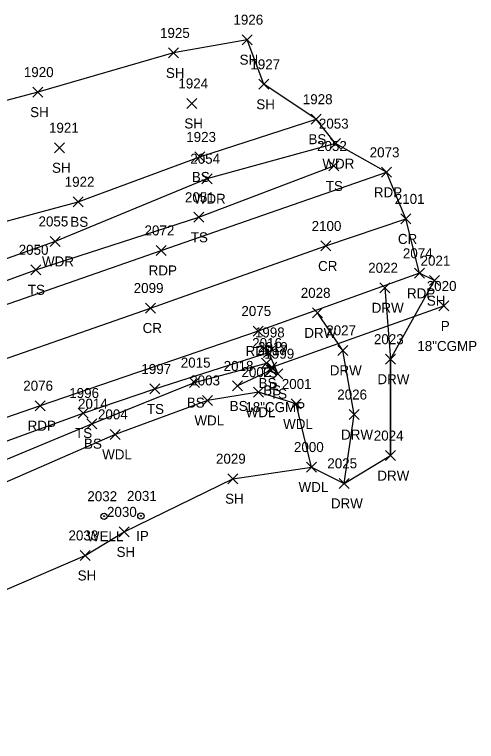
# Model space of a CAD drawing. Extents: x 1526508 to 1531550, y 369926 to 373082.
# Drawn here: x 1531457.6 to 1531549.9, y 370192.4 to 370337.7 of the extents above; entities that cross this region are included whole.
import ezdxf

# ---------------------------------------------------------------- set-up
doc = ezdxf.new("R2010")
doc.units = 0
for name, color, linetype in [('D_A', 7, 'Continuous'), ('D_C', 7, 'Continuous'), ('D_I', 7, 'Continuous'), ('D_TIC', 7, 'Continuous'), ('DCP', 7, 'Continuous'), ('L_A', 7, 'Continuous'), ('L_I', 7, 'Continuous'), ('L_TIC', 7, 'Continuous'), ('LAWA', 7, 'Continuous'), ('LELB', 7, 'Continuous'), ('LSOGP', 7, 'Continuous'), ('M_A', 7, 'Continuous'), ('M_I', 7, 'Continuous'), ('MPIR', 7, 'Continuous'), ('P_A', 7, 'Continuous'), ('P_I', 7, 'Continuous'), ('P_TIC', 7, 'Continuous'), ('PET', 7, 'Continuous'), ('PRC', 7, 'Continuous'), ('R_A', 7, 'Continuous'), ('R_I', 7, 'Continuous'), ('R_TIC', 7, 'Continuous'), ('RDW', 7, 'Continuous'), ('U_A', 7, 'Continuous'), ('U_I', 7, 'Continuous'), ('UWW', 7, 'Continuous')]:
    doc.layers.add(name, color=color, linetype=linetype)

msp = doc.modelspace()

# ---------------------------------------------------------------- linework, layer by layer
at = {"layer": 'D_TIC'}
for points in [[(1531542.39, 370278.49), (1531544.39, 370280.49)], [(1531544.39, 370278.49), (1531542.39, 370280.49)], [(1531508.03, 370266.27), (1531510.03, 370268.27)], [(1531510.03, 370266.27), (1531508.03, 370268.27)]]:
    msp.add_lwpolyline(points, dxfattribs=at)
at = {"layer": 'DCP'}
msp.add_lwpolyline([(1531509.03, 370267.27), (1531543.39, 370279.49)], dxfattribs=at)
at = {"layer": 'L_TIC'}
for points in [[(1531503.1, 370331.72), (1531505.1, 370333.72)], [(1531505.1, 370331.72), (1531503.1, 370333.72)], [(1531488.37, 370329.07), (1531490.37, 370331.07)], [(1531490.37, 370329.07), (1531488.37, 370331.07)], [(1531506.43, 370322.8), (1531508.43, 370324.8)], [(1531508.43, 370322.8), (1531506.43, 370324.8)], [(1531461.26, 370321.24), (1531463.26, 370323.24)], [(1531463.26, 370321.24), (1531461.26, 370323.24)], [(1531492.05, 370318.97), (1531494.05, 370320.97)], [(1531494.05, 370318.97), (1531492.05, 370320.97)], [(1531516.9, 370315.82), (1531518.9, 370317.82)], [(1531518.9, 370315.82), (1531516.9, 370317.82)], [(1531520.76, 370310.94), (1531522.76, 370312.94)], [(1531522.76, 370310.94), (1531520.76, 370312.94)], [(1531465.62, 370310.11), (1531467.62, 370312.11)], [(1531467.62, 370310.11), (1531465.62, 370312.11)], [(1531493.61, 370308.28), (1531495.61, 370310.28)], [(1531495.61, 370308.28), (1531493.61, 370310.28)], [(1531520.4, 370306.47), (1531522.4, 370308.47)], [(1531522.4, 370306.47), (1531520.4, 370308.47)], [(1531495.07, 370303.92), (1531497.07, 370305.92)], [(1531497.07, 370303.92), (1531495.07, 370305.92)], [(1531469.33, 370299.31), (1531471.33, 370301.31)], [(1531471.33, 370299.31), (1531469.33, 370301.31)], [(1531493.43, 370296.22), (1531495.43, 370298.22)], [(1531495.43, 370296.22), (1531493.43, 370298.22)], [(1531464.75, 370291.39), (1531466.75, 370293.39)], [(1531466.75, 370291.39), (1531464.75, 370293.39)], [(1531460.87, 370285.72), (1531462.87, 370287.72)], [(1531462.87, 370285.72), (1531460.87, 370287.72)], [(1531540.51, 370283.55), (1531542.51, 370285.55)], [(1531542.51, 370283.55), (1531540.51, 370285.55)], [(1531507.33, 370269.2), (1531509.33, 370271.2)], [(1531509.33, 370269.2), (1531507.33, 370271.2)], [(1531506.93, 370267.08), (1531508.93, 370269.08)], [(1531508.93, 370267.08), (1531506.93, 370269.08)], [(1531507.86, 370265.64), (1531509.86, 370267.64)], [(1531509.86, 370265.64), (1531507.86, 370267.64)], [(1531509.24, 370264.95), (1531511.24, 370266.95)], [(1531511.24, 370264.95), (1531509.24, 370266.95)], [(1531492.6, 370263.17), (1531494.6, 370265.17)], [(1531494.6, 370263.17), (1531492.6, 370265.17)], [(1531484.65, 370261.9), (1531486.65, 370263.9)], [(1531486.65, 370261.9), (1531484.65, 370263.9)], [(1531501.17, 370262.5), (1531503.17, 370264.5)], [(1531503.17, 370262.5), (1531501.17, 370264.5)], [(1531505.38, 370261.26), (1531507.38, 370263.26)], [(1531507.38, 370261.26), (1531505.38, 370263.26)], [(1531495.14, 370259.61), (1531497.14, 370261.61)], [(1531497.14, 370259.61), (1531495.14, 370261.61)], [(1531512.86, 370258.9), (1531514.86, 370260.9)], [(1531514.86, 370258.9), (1531512.86, 370260.9)], [(1531470.3, 370257.09), (1531472.3, 370259.09)], [(1531472.3, 370257.09), (1531470.3, 370259.09)], [(1531472.07, 370254.96), (1531474.07, 370256.96)], [(1531474.07, 370254.96), (1531472.07, 370256.96)], [(1531476.71, 370252.82), (1531478.71, 370254.82)], [(1531478.71, 370252.82), (1531476.71, 370254.82)], [(1531515.95, 370246.29), (1531517.95, 370248.29)], [(1531517.95, 370246.29), (1531515.95, 370248.29)], [(1531500.2, 370243.96), (1531502.2, 370245.96)], [(1531502.2, 370243.96), (1531500.2, 370245.96)], [(1531478.51, 370233.33), (1531480.51, 370235.33)], [(1531480.51, 370233.33), (1531478.51, 370235.33)], [(1531470.74, 370228.62), (1531472.74, 370230.62)], [(1531472.74, 370228.62), (1531470.74, 370230.62)]]:
    msp.add_lwpolyline(points, dxfattribs=at)
at = {"layer": 'LAWA'}
for points in [[(1531521.76, 370311.94), (1531496.07, 370304.92), (1531465.75, 370292.39), (1531436.88, 370282.15), (1531407.49, 370272.6), (1531388.76, 370267.94), (1531371.46, 370261.74), (1531353.51, 370253.07)], [(1531516.95, 370247.29), (1531513.86, 370259.9), (1531506.38, 370262.26), (1531496.14, 370260.61), (1531477.71, 370253.82), (1531453.39, 370243.21), (1531431.41, 370234.22), (1531411.87, 370226.08), (1531392.93, 370218.41), (1531374.28, 370205.66)]]:
    msp.add_lwpolyline(points, dxfattribs=at)
at = {"layer": 'LELB'}
for points in [[(1531144.65, 370206.06), (1531164.57, 370210.72), (1531180.3, 370218.31), (1531196.61, 370223.05), (1531216.18, 370227.2), (1531246.26, 370234.32), (1531259.5, 370237.9), (1531291.92, 370247.44), (1531321.67, 370253.97), (1531341.88, 370260.29), (1531377.42, 370272.37), (1531403.24, 370281.83), (1531425.1, 370287.02), (1531443.59, 370293.1), (1531470.33, 370300.31), (1531494.61, 370309.28), (1531517.9, 370316.82)], [(1531363.93, 370252.47), (1531390.95, 370261.46), (1531419.32, 370270.89), (1531442.26, 370279.58), (1531461.87, 370286.72), (1531494.43, 370297.22), (1531521.4, 370307.47)], [(1531373.54, 370214.88), (1531392.5, 370225.12), (1531411.75, 370234.05), (1531446.79, 370249.15), (1531471.3, 370258.09), (1531485.65, 370262.9), (1531508.33, 370270.2), (1531510.24, 370265.95)], [(1531371.86, 370211.77), (1531393.12, 370222.78), (1531419.45, 370234.98), (1531448.33, 370245.69), (1531473.07, 370255.96), (1531493.6, 370264.17), (1531507.93, 370268.08), (1531508.86, 370266.64), (1531502.17, 370263.5)]]:
    msp.add_lwpolyline(points, dxfattribs=at)
at = {"layer": 'LSOGP'}
msp.add_lwpolyline([(1531434.17, 370213.44), (1531471.74, 370229.62), (1531479.51, 370234.33), (1531501.2, 370244.96), (1531516.95, 370247.29), (1531523.45, 370244.03), (1531532.73, 370249.58), (1531532.74, 370259.21), (1531532.75, 370268.85), (1531541.51, 370284.55), (1531538.54, 370286.02), (1531535.78, 370296.89), (1531531.91, 370306.21), (1531521.76, 370311.94), (1531517.9, 370316.82), (1531507.43, 370323.8), (1531504.1, 370332.72), (1531489.37, 370330.07), (1531462.26, 370322.24), (1531445.4, 370317.76)], dxfattribs=at)
at = {"layer": 'MPIR'}
for radius in [0.625, 0.0833]:
    msp.add_circle((1531482.86, 370237.52), radius, dxfattribs=at)
at = {"layer": 'P_TIC'}
for points in [[(1531530.91, 370305.21), (1531532.91, 370307.21)], [(1531532.91, 370305.21), (1531530.91, 370307.21)], [(1531534.78, 370295.89), (1531536.78, 370297.89)], [(1531536.78, 370295.89), (1531534.78, 370297.89)], [(1531485.93, 370289.59), (1531487.93, 370291.59)], [(1531487.93, 370289.59), (1531485.93, 370291.59)], [(1531518.83, 370290.48), (1531520.83, 370292.48)], [(1531520.83, 370290.48), (1531518.83, 370292.48)], [(1531537.54, 370285.02), (1531539.54, 370287.02)], [(1531539.54, 370285.02), (1531537.54, 370287.02)], [(1531483.78, 370278.08), (1531485.78, 370280.08)], [(1531485.78, 370278.08), (1531483.78, 370280.08)], [(1531505.28, 370273.48), (1531507.28, 370275.48)], [(1531507.28, 370273.48), (1531505.28, 370275.48)], [(1531461.76, 370258.55), (1531463.76, 370260.55)], [(1531463.76, 370258.55), (1531461.76, 370260.55)]]:
    msp.add_lwpolyline(points, dxfattribs=at)
at = {"layer": 'PET'}
for points in [[(1531036.19, 370150.91), (1531061.97, 370155.43), (1531104.8, 370164.58), (1531143.1, 370174.02), (1531180.11, 370184.91), (1531218.48, 370196.81), (1531260.06, 370210.9), (1531302.03, 370225.36), (1531352.57, 370243.2), (1531401.62, 370260.1), (1531448.12, 370277.05), (1531486.93, 370290.59), (1531531.91, 370306.21)], [(1531538.54, 370286.02), (1531506.28, 370274.48), (1531462.76, 370259.55), (1531429.61, 370248.08), (1531393.11, 370234.63), (1531350.62, 370219.92), (1531310.67, 370205.95), (1531271.31, 370192.3), (1531228.45, 370178.01), (1531188.4, 370165.28), (1531155.96, 370155.78), (1531116.2, 370145.37), (1531081.97, 370137.61), (1531057.06, 370132.93), (1531039.15, 370130.45)]]:
    msp.add_lwpolyline(points, dxfattribs=at)
at = {"layer": 'PRC'}
msp.add_lwpolyline([(1531037.76, 370140.53), (1531081.39, 370148.17), (1531130.61, 370160.04), (1531176.3, 370172.81), (1531216.72, 370185.49), (1531265.37, 370201.61), (1531315.14, 370219.14), (1531364.47, 370236.54), (1531403.01, 370250.24), (1531441.26, 370263.86), (1531484.78, 370279.08), (1531519.83, 370291.48), (1531535.78, 370296.89)], dxfattribs=at)
at = {"layer": 'R_TIC'}
for points in [[(1531530.61, 370282.12), (1531532.61, 370284.12)], [(1531532.61, 370282.12), (1531530.61, 370284.12)], [(1531517.14, 370277.11), (1531519.14, 370279.11)], [(1531519.14, 370277.11), (1531517.14, 370279.11)], [(1531522.23, 370269.62), (1531524.23, 370271.62)], [(1531524.23, 370269.62), (1531522.23, 370271.62)], [(1531531.75, 370267.85), (1531533.75, 370269.85)], [(1531533.75, 370267.85), (1531531.75, 370269.85)], [(1531524.48, 370256.78), (1531526.48, 370258.78)], [(1531526.48, 370256.78), (1531524.48, 370258.78)], [(1531531.73, 370248.58), (1531533.73, 370250.58)], [(1531533.73, 370248.58), (1531531.73, 370250.58)], [(1531522.45, 370243.03), (1531524.45, 370245.03)], [(1531524.45, 370243.03), (1531522.45, 370245.03)]]:
    msp.add_lwpolyline(points, dxfattribs=at)
at = {"layer": 'RDW'}
for points in [[(1531531.61, 370283.12), (1531532.75, 370268.85), (1531532.73, 370249.58)], [(1531523.45, 370244.03), (1531525.48, 370257.78), (1531523.23, 370270.62), (1531518.14, 370278.11)]]:
    msp.add_lwpolyline(points, dxfattribs=at)
at = {"layer": 'UWW'}
for radius in [0.625, 0.0833]:
    msp.add_circle((1531475.51, 370237.46), radius, dxfattribs=at)

# ---------------------------------------------------------------- texts
at = {"layer": 'D_A'}
for p in [(1531542.77, 370274.49), (1531508.41, 370262.27)]:
    msp.add_text('P', height=2, dxfattribs=at).set_placement(p)
at = {"layer": 'D_C'}
for p in [(1531538.09, 370270.49), (1531503.73, 370258.27)]:
    msp.add_text('18"CGMP', height=2, dxfattribs=at).set_placement(p)
at = {"layer": 'D_I'}
for s, p in [('2020', (1531539.97, 370282.49)), ('2019', (1531506.25, 370270.27))]:
    msp.add_text(s, height=2, dxfattribs=at).set_placement(p)
at = {"layer": 'L_A'}
for s, p in [('SH', (1531502.58, 370327.72)), ('SH', (1531487.86, 370325.07)), ('SH', (1531505.92, 370318.8)), ('SH', (1531460.74, 370317.24)), ('SH', (1531491.54, 370314.97)), ('BS', (1531516.34, 370311.82)), ('WDR', (1531519.12, 370306.94)), ('SH', (1531465.11, 370306.11)), ('BS', (1531493.05, 370304.28)), ('TS', (1531519.81, 370302.47)), ('WDR', (1531493.43, 370299.92)), ('BS', (1531468.77, 370295.31)), ('TS', (1531492.84, 370292.22)), ('WDR', (1531463.11, 370287.39)), ('TS', (1531460.28, 370281.72)), ('SH', (1531539.99, 370279.55)), ('TS', (1531506.74, 370265.2)), ('BS', (1531506.37, 370263.08)), ('BS', (1531507.3, 370261.64)), ('TS', (1531508.65, 370260.95)), ('BS', (1531492.04, 370259.17)), ('TS', (1531484.06, 370257.9)), ('BS', (1531500.61, 370258.5)), ('WDL', (1531503.79, 370257.26)), ('WDL', (1531493.56, 370255.61)), ('WDL', (1531511.28, 370254.9)), ('TS', (1531469.71, 370253.09)), ('BS', (1531471.51, 370250.96)), ('WDL', (1531475.13, 370248.82)), ('WDL', (1531514.36, 370242.29)), ('SH', (1531499.69, 370239.96)), ('SH', (1531478, 370229.33)), ('SH', (1531470.23, 370224.62))]:
    msp.add_text(s, height=2, dxfattribs=at).set_placement(p)
at = {"layer": 'L_I'}
for s, p in [('1926', (1531501.35, 370335.72)), ('1925', (1531486.68, 370333.07)), ('1927', (1531504.73, 370326.8)), ('1920', (1531459.48, 370325.24)), ('1924', (1531490.35, 370322.97)), ('1928', (1531515.21, 370319.82)), ('1921', (1531464.5, 370314.11)), ('2053', (1531518.42, 370314.94)), ('1923', (1531491.92, 370312.28)), ('2052', (1531518.06, 370310.47)), ('2054', (1531492.73, 370307.92)), ('1922', (1531467.64, 370303.31)), ('2051', (1531491.66, 370300.22)), ('2055', (1531462.41, 370295.39)), ('2050', (1531458.45, 370289.72)), ('2021', (1531538.73, 370287.55)), ('1998', (1531505.64, 370273.2)), ('2016', (1531505.1, 370271.08)), ('2017', (1531506.09, 370269.64)), ('1999', (1531507.54, 370268.95)), ('1997', (1531482.96, 370265.9)), ('2015', (1531490.83, 370267.17)), ('2018', (1531499.4, 370266.5)), ('2002', (1531502.96, 370265.26)), ('2003', (1531492.72, 370263.61)), ('2001', (1531511.01, 370262.9)), ('1996', (1531468.55, 370261.09)), ('2014', (1531470.3, 370258.96)), ('2004', (1531474.29, 370256.82)), ('2000', (1531513.44, 370250.29)), ('2029', (1531497.86, 370247.96)), ('2030', (1531476.09, 370237.33)), ('2033', (1531468.4, 370232.62))]:
    msp.add_text(s, height=2, dxfattribs=at).set_placement(p)
at = {"layer": 'M_A'}
msp.add_text('IP', height=2, dxfattribs=at).set_placement((1531481.91, 370232.52))
at = {"layer": 'M_I'}
msp.add_text('2031', height=2, dxfattribs=at).set_placement((1531480.09, 370240.52))
at = {"layer": 'P_A'}
for s, p in [('RDP', (1531529.4, 370301.21)), ('CR', (1531534.21, 370291.89)), ('CR', (1531518.26, 370286.48)), ('RDP', (1531484.42, 370285.59)), ('RDP', (1531536.02, 370281.02)), ('CR', (1531483.21, 370274.08)), ('RDP', (1531503.77, 370269.48)), ('RDP', (1531460.25, 370254.55))]:
    msp.add_text(s, height=2, dxfattribs=at).set_placement(p)
at = {"layer": 'P_I'}
for s, p in [('2073', (1531528.57, 370309.21)), ('2101', (1531533.58, 370299.89)), ('2072', (1531483.59, 370293.59)), ('2100', (1531516.97, 370294.48)), ('2074', (1531535.2, 370289.02)), ('2099', (1531481.43, 370282.08)), ('2075', (1531502.94, 370277.48)), ('2076', (1531459.36, 370262.55))]:
    msp.add_text(s, height=2, dxfattribs=at).set_placement(p)
at = {"layer": 'R_A'}
for p in [(1531528.98, 370278.12), (1531515.51, 370273.11), (1531520.6, 370265.62), (1531530.12, 370263.85), (1531522.85, 370252.78), (1531530.1, 370244.58), (1531520.82, 370239.03)]:
    msp.add_text('DRW', height=2, dxfattribs=at).set_placement(p)
at = {"layer": 'R_I'}
for s, p in [('2022', (1531528.27, 370286.12)), ('2028', (1531514.8, 370281.11)), ('2027', (1531519.89, 370273.62)), ('2023', (1531529.42, 370271.85)), ('2026', (1531522.09, 370260.78)), ('2024', (1531529.39, 370252.58)), ('2025', (1531520.11, 370247.03))]:
    msp.add_text(s, height=2, dxfattribs=at).set_placement(p)
at = {"layer": 'U_A'}
msp.add_text('WELL', height=2, dxfattribs=at).set_placement((1531472.08, 370232.46))
at = {"layer": 'U_I'}
msp.add_text('2032', height=2, dxfattribs=at).set_placement((1531472.17, 370240.46))

doc.saveas('drawing.dxf')
